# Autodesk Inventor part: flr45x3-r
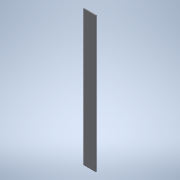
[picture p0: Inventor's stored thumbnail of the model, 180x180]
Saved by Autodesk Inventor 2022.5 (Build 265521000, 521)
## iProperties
Created: 2016-12
Part Number: flr45x3-r
Material: 一般
Document SubType Name: Modeling
Designer: imaocorp
Density: 1 g/cm^3
Appearance: 既定
Author: imaocorp
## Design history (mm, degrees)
node "flr45x3-r.x_t1"
node "flr45x3-r"
node "Base1"
